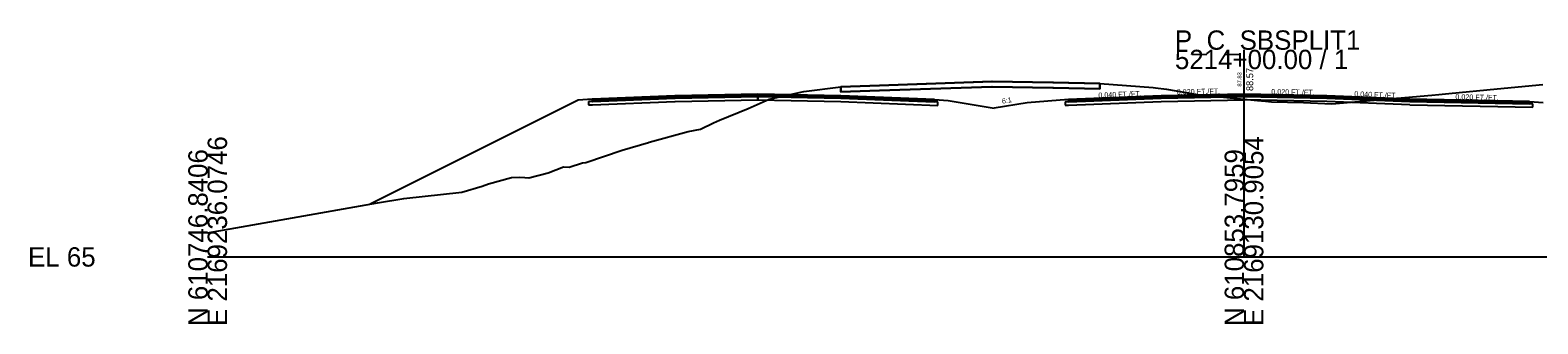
# Model space of a CAD drawing. Extents: x -26 to 1303, y -3010 to 12033.
# Drawn here: x 974.3 to 1192.5, y 8990.3 to 9032.8 of the extents above; entities that cross this region are included whole.
import ezdxf

# ---------------------------------------------------------------- set-up
doc = ezdxf.new("R2010")
doc.units = 0
for name, color, linetype in [('RD_GPK_XS_Cell', 7, 'Continuous'), ('RD_XS_Base', 7, 'Continuous'), ('RD_XS_ExGround', 7, 'Continuous'), ('RD_XS_ExPaveRet', 7, 'Continuous'), ('RD_XS_Greenside', 7, 'Continuous'), ('RD_XS_Pave', 7, 'Continuous'), ('RD_XS_PaveOvlay_CP', 7, 'Continuous'), ('RD_XS_TieSlope', 7, 'Continuous'), ('RD_XS_TX_Elev_EX', 7, 'Continuous'), ('RD_XS_TX_Elev_PR', 7, 'Continuous'), ('RD_XS_TX_Slope', 7, 'Continuous')]:
    doc.layers.add(name, color=color, linetype=linetype)

msp = doc.modelspace()

# ---------------------------------------------------------------- linework, layer by layer
at = {"layer": 'RD_GPK_XS_Cell'}
for p, q in [((1150, 9000), (1150, 9030)), ((1000, 9000), (1150, 9000)), ((1150, 9000), (1300, 9000))]:
    msp.add_line(p, q, dxfattribs=at)
at = {"layer": 'RD_XS_Base'}
for p, q in [((1055.64, 9022.53), (1055.14, 9022.51)), ((1055.14, 9022.51), (1055.14, 9022.51)), ((1055.14, 9022.51), (1055.14, 9022.01)), ((1055.14, 9022.01), (1055.64, 9022.03)), ((1055.14, 9022.01), (1055.14, 9022.01)), ((1055.14, 9022.01), (1055.14, 9022.01)), ((1055.69, 9022.53), (1055.64, 9022.53)), ((1055.64, 9022.03), (1055.69, 9022.03)), ((1067.64, 9023.01), (1055.69, 9022.53)), ((1055.69, 9022.03), (1067.64, 9022.51)), ((1067.67, 9023.01), (1067.64, 9023.01)), ((1067.64, 9022.51), (1067.67, 9022.51)), ((1079.64, 9023.25), (1067.67, 9023.01)), ((1067.67, 9022.51), (1079.64, 9022.75)), ((1079.64, 9022.75), (1079.64, 9023.41)), ((1079.64, 9023.41), (1079.64, 9023.25)), ((1079.64, 9023.25), (1079.64, 9023.41)), ((1079.64, 9023.41), (1079.64, 9023.41)), ((1079.64, 9023.41), (1079.64, 9023.41)), ((1079.64, 9023.41), (1079.64, 9022.75)), ((1079.64, 9022.75), (1079.64, 9023.25)), ((1079.64, 9023.25), (1079.64, 9023.25)), ((1079.64, 9022.75), (1079.64, 9023.25)), ((1079.64, 9023.25), (1079.64, 9023.25)), ((1079.64, 9023.25), (1079.64, 9023.25)), ((1079.64, 9023.25), (1079.64, 9023.25)), ((1091.64, 9023.01), (1079.64, 9023.25)), ((1079.64, 9022.75), (1079.64, 9022.75)), ((1079.64, 9022.75), (1079.64, 9022.75)), ((1079.64, 9022.75), (1079.64, 9022.75)), ((1079.64, 9022.75), (1079.64, 9022.75)), ((1079.64, 9022.75), (1091.64, 9022.51)), ((1105.19, 9022.47), (1091.64, 9023.01)), ((1091.64, 9022.51), (1105.69, 9021.95)), ((1093.64, 9022.93), (1093.64, 9022.93)), ((1093.64, 9022.43), (1093.64, 9022.43)), ((1105.69, 9022.45), (1105.19, 9022.47)), ((1105.19, 9022.47), (1105.19, 9022.47)), ((1105.69, 9021.95), (1105.69, 9022.45)), ((1105.69, 9022.45), (1105.69, 9022.45)), ((1124.61, 9022.48), (1124.11, 9022.46)), ((1124.11, 9022.46), (1124.11, 9022.46)), ((1124.11, 9022.46), (1124.11, 9021.96)), ((1124.11, 9021.96), (1124.61, 9021.98)), ((1138, 9023.01), (1124.61, 9022.48)), ((1124.61, 9021.98), (1138, 9022.51)), ((1124.61, 9022.48), (1124.61, 9022.48)), ((1124.61, 9021.98), (1124.61, 9021.98)), ((1150, 9023.25), (1138, 9023.01)), ((1138, 9022.51), (1150, 9022.75)), ((1150, 9022.75), (1150, 9023.41)), ((1150, 9023.41), (1150, 9023.41)), ((1150, 9023.41), (1150, 9023.41)), ((1150, 9023.41), (1150, 9023.25)), ((1150, 9022.75), (1150, 9023.25)), ((1150, 9023.25), (1150, 9023.25)), ((1150, 9023.25), (1150, 9023.25)), ((1150, 9023.25), (1150, 9023.25)), ((1150, 9023.25), (1162, 9023.01)), ((1150, 9023.25), (1150, 9023.25)), ((1150, 9022.75), (1150, 9022.75)), ((1162, 9022.51), (1150, 9022.75)), ((1150, 9022.75), (1150, 9022.75)), ((1162, 9023.01), (1162, 9023.01)), ((1162, 9023.01), (1174, 9022.53)), ((1174, 9022.03), (1162, 9022.51)), ((1162, 9022.51), (1162, 9022.51)), ((1191.3, 9022.19), (1174, 9022.53)), ((1174, 9022.53), (1174, 9022.53)), ((1174, 9022.03), (1174, 9022.03)), ((1174, 9022.03), (1191.8, 9021.68)), ((1191.8, 9022.18), (1191.3, 9022.19)), ((1191.3, 9022.19), (1191.3, 9022.19)), ((1191.8, 9021.68), (1191.8, 9022.18)), ((1191.8, 9022.18), (1191.8, 9022.18)), ((1191.8, 9021.68), (1191.8, 9021.68)), ((1191.8, 9021.68), (1191.8, 9021.68))]:
    msp.add_line(p, q, dxfattribs=at)
at = {"layer": 'RD_XS_ExGround'}
msp.add_lwpolyline([(1000, 9003.49), (1024.59, 9007.82), (1028.4, 9008.47), (1036.78, 9009.39), (1039.74, 9010.24), (1040.64, 9010.58), (1043.97, 9011.51), (1045.18, 9011.57), (1045.91, 9011.51), (1046.47, 9011.47), (1049.29, 9012.18), (1051.49, 9013.03), (1052.34, 9013.02), (1054.27, 9013.63), (1054.73, 9013.66), (1060.01, 9015.45), (1063.81, 9016.58), (1063.82, 9016.58), (1063.83, 9016.58), (1063.9, 9016.6), (1069.55, 9018.18), (1071.35, 9018.52), (1073.22, 9019.4), (1074.07, 9019.79), (1078.24, 9021.5), (1081.25, 9022.86), (1086.27, 9023.98), (1091.63, 9024.65), (1097.25, 9024.84), (1113.54, 9025.39), (1122.34, 9025.24), (1129.14, 9025.11), (1136.85, 9024.53), (1137.21, 9024.5), (1138.76, 9024.27), (1143.25, 9023.51), (1147.04, 9023.13), (1151.95, 9022.66), (1153.09, 9022.54), (1153.98, 9022.48), (1158.59, 9022.34), (1162.7, 9022.15), (1177.18, 9023.42), (1178.21, 9023.5), (1179.63, 9023.65), (1186.62, 9024.32), (1193.26, 9024.98)], dxfattribs=at)
at = {"layer": 'RD_XS_ExPaveRet'}
for points in [[(1129.14, 9025.11), (1129.14, 9025.11), (1129.14, 9024.37), (1129.14, 9024.36), (1129.14, 9024.36), (1129.14, 9024.36), (1122.41, 9024.49), (1122.34, 9024.49), (1113.57, 9024.63), (1113.54, 9024.64), (1113.48, 9024.63), (1097.25, 9024.09), (1097.22, 9024.09), (1091.63, 9023.9), (1091.63, 9023.9), (1091.63, 9023.9), (1091.63, 9023.91), (1091.63, 9024.65), (1091.63, 9024.65), (1091.63, 9024.65), (1097.22, 9024.84), (1097.25, 9024.84), (1113.48, 9025.38), (1113.54, 9025.39), (1113.57, 9025.38), (1122.34, 9025.24), (1122.41, 9025.24), (1129.14, 9025.11), (1129.14, 9025.11)], [(1129.14, 9025.11), (1122.41, 9025.24), (1122.34, 9025.24), (1113.57, 9025.38), (1113.54, 9025.39), (1113.48, 9025.38), (1097.25, 9024.84), (1097.22, 9024.84), (1091.63, 9024.65), (1091.63, 9023.91), (1091.63, 9023.9), (1097.22, 9024.09), (1097.25, 9024.09), (1113.48, 9024.63), (1113.54, 9024.64), (1113.57, 9024.63), (1122.34, 9024.49), (1122.41, 9024.49), (1129.14, 9024.36), (1129.14, 9024.36), (1129.14, 9024.37), (1129.14, 9025.11), (1129.14, 9025.11)]]:
    msp.add_lwpolyline(points, dxfattribs=at)
at = {"layer": 'RD_XS_Greenside'}
for p, q in [((1053.64, 9022.69), (1023.52, 9007.63)), ((1107.19, 9022.63), (1113.84, 9021.52)), ((1118.61, 9022.31), (1113.84, 9021.52))]:
    msp.add_line(p, q, dxfattribs=at)
at = {"layer": 'RD_XS_Pave'}
for p, q in [((1079.64, 9023.57), (1067.67, 9023.33)), ((1091.64, 9023.33), (1079.64, 9023.57)), ((1079.64, 9023.57), (1079.64, 9023.57)), ((1079.64, 9023.57), (1079.64, 9023.57)), ((1150, 9023.57), (1138, 9023.33)), ((1162, 9023.33), (1150, 9023.57)), ((1150, 9023.57), (1150, 9023.57)), ((1150, 9023.57), (1150, 9023.57)), ((1055.69, 9022.85), (1055.64, 9022.85)), ((1055.64, 9022.85), (1055.64, 9022.69)), ((1055.69, 9022.69), (1055.64, 9022.69)), ((1055.64, 9022.69), (1055.64, 9022.53)), ((1055.64, 9022.69), (1055.64, 9022.69)), ((1055.64, 9022.69), (1055.69, 9022.69)), ((1055.64, 9022.53), (1055.64, 9022.53)), ((1055.64, 9022.53), (1055.69, 9022.53)), ((1067.64, 9023.33), (1055.69, 9022.85)), ((1067.64, 9023.17), (1055.69, 9022.69)), ((1055.69, 9022.69), (1067.64, 9023.17)), ((1055.69, 9022.53), (1067.64, 9023.01)), ((1067.67, 9023.33), (1067.64, 9023.33)), ((1067.67, 9023.17), (1067.64, 9023.17)), ((1067.64, 9023.17), (1067.67, 9023.17)), ((1067.64, 9023.01), (1067.67, 9023.01)), ((1079.64, 9023.41), (1067.67, 9023.17)), ((1067.67, 9023.17), (1079.64, 9023.41)), ((1067.67, 9023.01), (1079.64, 9023.25)), ((1079.64, 9023.25), (1079.64, 9023.41)), ((1079.64, 9023.25), (1079.64, 9023.41)), ((1079.64, 9023.25), (1079.64, 9023.41)), ((1079.64, 9023.41), (1079.64, 9023.41)), ((1079.64, 9023.41), (1079.64, 9023.41)), ((1079.64, 9023.41), (1079.64, 9023.41)), ((1079.64, 9023.41), (1079.64, 9023.41)), ((1079.64, 9023.41), (1091.64, 9023.17)), ((1091.64, 9023.17), (1079.64, 9023.41)), ((1079.64, 9023.41), (1079.64, 9023.41)), ((1079.64, 9023.41), (1079.64, 9023.41)), ((1079.64, 9023.41), (1079.64, 9023.25)), ((1079.64, 9023.25), (1079.64, 9023.25)), ((1079.64, 9023.25), (1079.64, 9023.25)), ((1079.64, 9023.25), (1079.64, 9023.25)), ((1079.64, 9023.25), (1079.64, 9023.25)), ((1079.64, 9023.25), (1091.64, 9023.01)), ((1105.19, 9022.79), (1091.64, 9023.33)), ((1091.64, 9023.17), (1105.19, 9022.63)), ((1105.19, 9022.63), (1091.64, 9023.17)), ((1091.64, 9023.01), (1105.19, 9022.47)), ((1093.64, 9023.25), (1093.64, 9023.25)), ((1093.64, 9023.09), (1093.64, 9023.09)), ((1093.64, 9023.09), (1093.64, 9023.09)), ((1093.64, 9022.93), (1093.64, 9022.93)), ((1105.19, 9022.63), (1105.19, 9022.79)), ((1105.19, 9022.79), (1105.19, 9022.79)), ((1105.19, 9022.47), (1105.19, 9022.63)), ((1105.19, 9022.63), (1105.19, 9022.63)), ((1138, 9023.33), (1124.61, 9022.79)), ((1138, 9023.17), (1124.61, 9022.64)), ((1124.61, 9022.64), (1138, 9023.17)), ((1124.61, 9022.48), (1138, 9023.01)), ((1124.61, 9022.79), (1124.61, 9022.79)), ((1124.61, 9022.79), (1124.61, 9022.64)), ((1124.61, 9022.64), (1124.61, 9022.64)), ((1124.61, 9022.64), (1124.61, 9022.48)), ((1150, 9023.41), (1138, 9023.17)), ((1138, 9023.17), (1150, 9023.41)), ((1138, 9023.01), (1150, 9023.25)), ((1150, 9023.25), (1150, 9023.41)), ((1150, 9023.41), (1150, 9023.41)), ((1150, 9023.41), (1150, 9023.41)), ((1150, 9023.41), (1150, 9023.41)), ((1150, 9023.41), (1150, 9023.41)), ((1150, 9023.41), (1162, 9023.17)), ((1162, 9023.17), (1150, 9023.41)), ((1150, 9023.41), (1150, 9023.41)), ((1150, 9023.41), (1150, 9023.41)), ((1150, 9023.41), (1150, 9023.41)), ((1150, 9023.41), (1150, 9023.25)), ((1150, 9023.25), (1150, 9023.25)), ((1150, 9023.25), (1150, 9023.25)), ((1150, 9023.25), (1150, 9023.25)), ((1150, 9023.25), (1162, 9023.01)), ((1174, 9022.85), (1162, 9023.33)), ((1162, 9023.33), (1162, 9023.33)), ((1162, 9023.17), (1162, 9023.17)), ((1162, 9023.17), (1174, 9022.69)), ((1174, 9022.69), (1162, 9023.17)), ((1162, 9023.17), (1162, 9023.17)), ((1162, 9023.01), (1174, 9022.53)), ((1162, 9023.01), (1162, 9023.01)), ((1191.3, 9022.5), (1174, 9022.85)), ((1174, 9022.85), (1174, 9022.85)), ((1174, 9022.69), (1174, 9022.69)), ((1174, 9022.69), (1191.3, 9022.34)), ((1191.3, 9022.34), (1174, 9022.69)), ((1174, 9022.69), (1174, 9022.69)), ((1174, 9022.53), (1174, 9022.53)), ((1174, 9022.53), (1191.3, 9022.19)), ((1191.3, 9022.34), (1191.3, 9022.5)), ((1191.3, 9022.5), (1191.3, 9022.5)), ((1191.3, 9022.34), (1191.3, 9022.34)), ((1191.3, 9022.34), (1191.3, 9022.34)), ((1191.3, 9022.19), (1191.3, 9022.34)), ((1191.3, 9022.34), (1191.3, 9022.34)), ((1191.3, 9022.19), (1191.3, 9022.19)), ((1191.3, 9022.19), (1191.3, 9022.19))]:
    msp.add_line(p, q, dxfattribs=at)
at = {"layer": 'RD_XS_PaveOvlay_CP'}
for p, q in [((1067.64, 9023.33), (1079.64, 9023.57)), ((1079.64, 9023.57), (1091.64, 9023.33)), ((1150, 9023.57), (1138, 9023.33)), ((1162, 9023.33), (1150, 9023.57)), ((1150, 9023.57), (1150, 9023.57)), ((1150, 9023.57), (1150, 9023.57)), ((1055.64, 9022.85), (1067.64, 9023.33)), ((1091.64, 9023.33), (1105.19, 9022.79)), ((1138, 9023.33), (1124.61, 9022.79)), ((1174, 9022.85), (1162, 9023.33)), ((1162, 9023.33), (1162, 9023.33)), ((1191.3, 9022.5), (1174, 9022.85)), ((1174, 9022.85), (1174, 9022.85)), ((1191.3, 9022.5), (1191.3, 9022.5))]:
    msp.add_line(p, q, dxfattribs=at)
at = {"layer": 'RD_XS_TieSlope'}
for p, q in [((1055.64, 9022.85), (1053.64, 9022.69)), ((1105.19, 9022.79), (1107.19, 9022.63)), ((1124.61, 9022.79), (1118.61, 9022.31)), ((1191.3, 9022.5), (1193.3, 9022.34))]:
    msp.add_line(p, q, dxfattribs=at)

# ---------------------------------------------------------------- texts
at = {"layer": 'RD_GPK_XS_Cell'}
for s, p in [('P_C_SBSPLIT1', (1140, 9030)), ('5214+00.00 / 1', (1140, 9027.2)), ('EL 65', (974, 8998.6))]:
    msp.add_text(s, height=2.8, dxfattribs=at).set_placement(p)
for s, p in [('E 2169236.0746', (1002.8, 8990)), ('E 2169130.9054', (1152.8, 8990)), ('N 610746.8406', (1000, 8990)), ('N 610853.7959', (1150, 8990))]:
    msp.add_text(s, height=2.8, rotation=90, dxfattribs=at).set_placement(p)
at = {"layer": 'RD_XS_TX_Elev_EX'}
msp.add_text('87.83', height=0.6, rotation=90, dxfattribs=at).set_placement((1149.63, 9024.67))
at = {"layer": 'RD_XS_TX_Elev_PR'}
msp.add_text('88.57', height=1, rotation=90, dxfattribs=at).set_placement((1151.33, 9024.02))
at = {"layer": 'RD_XS_TX_Slope'}
for s, rotation, p in [('0.040 FT./FT.', 2.2906, (1128.93, 9023.04)), ('0.020 FT./FT.', 1.1458, (1140.27, 9023.52)), ('0.020 FT./FT.', 358.8542, (1153.94, 9023.57)), ('0.040 FT./FT.', 357.7094, (1165.94, 9023.25)), ('0.020 FT./FT.', 358.8542, (1180.59, 9022.82)), ('6:1', 9.4642, (1115.01, 9022.18))]:
    msp.add_text(s, height=0.75, rotation=rotation, dxfattribs=at).set_placement(p)

doc.saveas('drawing.dxf')
